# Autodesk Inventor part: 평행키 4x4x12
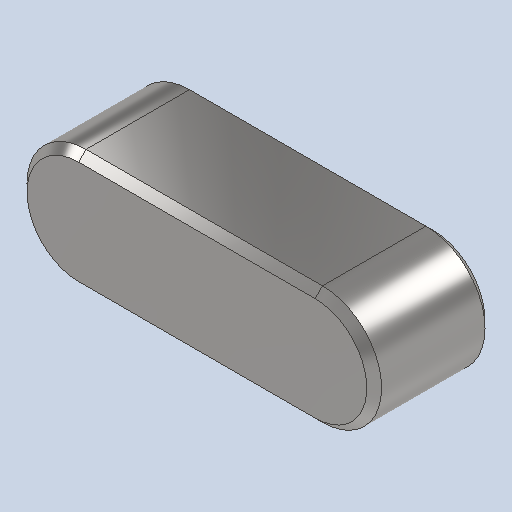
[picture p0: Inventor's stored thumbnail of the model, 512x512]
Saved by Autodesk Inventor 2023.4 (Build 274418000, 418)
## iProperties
Created: 2024-04
Part Number: 평행키 4x4x12
Material: 강철, 연강
Description: 키 및 해당 키홈
Document SubType Name: Modeling
Designer: Edu03
Density: 7.85 g/cm^3
Appearance: 기본값
Author: jhkim
Sending System: Autodesk Inventor 2025
Preprocessor: ST-DEVELOPER v20
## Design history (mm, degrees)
feature "Solid1"
node "솔리드1"
